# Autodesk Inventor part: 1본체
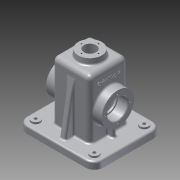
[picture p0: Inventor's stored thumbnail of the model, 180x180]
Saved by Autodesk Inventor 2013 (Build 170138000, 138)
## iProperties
Created: 2016-01
Part Number: 1본체
Material: 알루미늄 6061
Document SubType Name: Modeling
Designer: Administrator
Density: 2.71 g/cm^3
Mass: 927.953 g
Surface Area: 977.096 cm^2
Volume: 342.418 cm^3
Author: Administrator
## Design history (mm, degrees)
sketch "스케치1"
  geometry: L1 (32.5, -32.5)-(-32.5, -32.5); L2 (-32.5, -32.5)-(-32.5, 32.5); L3 (-32.5, 32.5)-(32.5, 32.5); L4 (32.5, 32.5)-(32.5, -32.5); L5 (32.5, -32.5)-(-32.5, 32.5); L6 (-32.5, -32.5)-(32.5, 32.5); 1 further point
  constraints: 12 end point, 2 midpoint, 2 parallel, 1 horizontal, 1 perpendicular
  dimensions: "d0" = 65 distance of L2.end L3.end; "d2" = 65 distance of L1.end L2.end
extrude "돌출1" new body sketch "스케치1" distance "d3" = 110; taper "d4" = 0 deg
feature "쉘1" dims "d5" = 5
sketch "스케치3"
  geometry: L1 (0, 65)-(0, 0) reference; C1 r 27.5 at (-55, 32.5); 2 further points
  constraints: 1 centre point, 1 horizontal alignment, 1 midpoint
  dimensions: "d6" = 55 diameter of C1; "d7" = 55 distance of point (0, 32.5) C1.centre
extrude "돌출2" join sketch "스케치3" distance "d8" = 15; taper "d9" = 0 deg
hole "구멍1" diameter "d12" = 30; stored, may be unused: countersink angle "d16" = 90 deg, drill point angle "d18" = 0 deg; dims "d10" = 10, "d11" = 10, "d13" = 6, "d14" = 35, "d15" = 17, "d17" = 8
sketch "스케치4"
  geometry: C1 r 17.5 at (0, 0) reference; 2 further points
  constraints: 1 horizontal alignment
  dimensions: "d19" = 21 distance of C1.centre point (-21, 0)
hole "구멍2" sketch "스케치4" at (-21, 0) diameter "d20" = 3.242; stored, may be unused: countersink angle "d24" = 90 deg, drill point angle "d26" = 118 deg; dims "d21" = 8, "d22" = 35, "d23" = 17, "d25" = 10
node "작업 평면1"
sketch "스케치5"
  geometry: C1 r 20 at (0, 0); 1 further point
  constraints: 1 centre point, 1 coincident
  dimensions: "d31" = 40 diameter of C1
extrude "돌출3" join sketch "스케치5" stored distance "d32" = 15; taper "d33" = 5 deg
sketch "스케치6"
  geometry: C1 r 20 at (0, 0) reference; C2 r 10.5 at (0, 0)
  constraints: 1 centre point, 1 coincident
  dimensions: "d34" = 21 diameter of C2
extrude "돌출4" cut sketch "스케치6" stored distance "d35" = 15; taper "d36" = 0 deg
sketch "스케치7"
  geometry: C1 r 10.5 at (0, 0) reference; 1 further point
  constraints: 1 horizontal alignment
  dimensions: "d37" = 14.5 distance of point (14.5, 0) C1.centre
hole "구멍3" sketch "스케치7" at (14.5, 0) diameter "d38" = 2.459; stored, may be unused: countersink angle "d42" = 90 deg, drill point angle "d44" = 118 deg; dims "d39" = 7, "d40" = 35, "d41" = 17, "d43" = 9
sketch "스케치8"
  geometry: L1 (-65, 57.5)-(65, 57.5); L2 (65, 57.5)-(65, -57.5); L3 (65, -57.5)-(-65, -57.5); L4 (-65, -57.5)-(-65, 57.5); L5 (-65, 57.5)-(65, -57.5); L6 (65, 57.5)-(-65, -57.5); 1 further point
  constraints: 12 end point, 2 midpoint, 2 parallel, 1 horizontal, 1 perpendicular
  dimensions: "d48" = 130 distance of L1.start L1.end; "d50" = 115 distance of L1.end L2.end
extrude "돌출5" join sketch "스케치8" distance "d51" = 10; taper "d52" = 0 deg
fillet "모깎기1" dims "d53" = 15
sketch "스케치10"
  geometry: C1 r 7.5 at (-50, 42.5); C2 r 7.5 at (50, 42.5); C3 r 7.5 at (50, -42.5); C4 r 7.5 at (-50, -42.5); A1 r 15 centre (50, -42.5) between (50, -57.5) and (65, -42.5) reference; A2 r 15 centre (50, 42.5) between (65, 42.5) and (50, 57.5) reference; A3 r 15 centre (-50, 42.5) between (-50, 57.5) and (-65, 42.5) reference; A4 r 15 centre (-50, -42.5) between (-65, -42.5) and (-50, -57.5) reference; 1 further point
  constraints: 4 centre point, 4 coincident
  dimensions: "d54" = 15 diameter of C1; "d55" = 15 diameter of C2; "d56" = 15 diameter of C3; "d57" = 15 diameter of C4
extrude "돌출6" join sketch "스케치10" distance "d58" = 3; taper "d59" = 0 deg
sketch "스케치11"
  geometry: L1 (-50, -57.5)-(50, -57.5) reference; L2 (65, -42.5)-(65, 42.5) reference; L3 (50, 57.5)-(-50, 57.5) reference; L4 (-65, 42.5)-(-65, -42.5) reference; L5 (50, -52.5)-(-50, -52.5); L6 (-60, -42.5)-(-60, 42.5); L7 (-50, 52.5)-(50, 52.5); L8 (60, 42.5)-(60, -42.5); A1 r 15 centre (-50, -42.5) between (-65, -42.5) and (-50, -57.5) reference; A2 r 15 centre (50, -42.5) between (50, -57.5) and (65, -42.5) reference; A3 r 15 centre (50, 42.5) between (65, 42.5) and (50, 57.5) reference; A4 r 15 centre (-50, 42.5) between (-50, 57.5) and (-65, 42.5) reference; A5 r 10 centre (-50, -42.5) between (-60, -42.5) and (-50, -52.5); A6 r 10 centre (-50, 42.5) between (-50, 52.5) and (-60, 42.5); A7 r 10 centre (50, 42.5) between (60, 42.5) and (50, 52.5); A8 r 10 centre (50, -42.5) between (50, -52.5) and (60, -42.5); 1 further point
  constraints: 8 end point, 8 point on circle, 4 centre point, 7 other
  dimensions: "d60" = 5 distance between parallel lines of L5 L1
extrude "돌출7" join sketch "스케치11" distance "d62" = 2; taper "d63" = 0 deg
sketch "스케치12"
  geometry: A1 r 10 centre (-50, -42.5) between (-60, -42.5) and (-50, -52.5) reference; A2 r 10 centre (50, -42.5) between (50, -52.5) and (60, -42.5) reference; A3 r 10 centre (50, 42.5) between (60, 42.5) and (50, 52.5) reference; A4 r 10 centre (-50, 42.5) between (-50, 52.5) and (-60, 42.5) reference; 1 further point
hole "구멍4" sketch "스케치12" at (50, -42.5), (-50, -42.5), (-50, 42.5), (50, 42.5) diameter "d64" = 5; stored, may be unused: countersink angle "d68" = 90 deg, drill point angle "d70" = 118 deg; dims "d65" = 7, "d66" = 35, "d67" = 17, "d69" = 9
sketch "스케치17"
  geometry: L1 (32.5, 82.5)-(47.5, 82.5) reference; L2 (47.5, 82.5)-(47.5, 77.621) reference; L3 (47.5, 77.621)-(37.5, 77.621) reference; L4 (37.5, 77.621)-(36.526, 76) reference; L5 (36.526, 76)-(37.5, 74.379) reference; L6 (37.5, 74.379)-(47.5, 74.379) reference; L7 (47.5, 74.379)-(47.5, 72.5) reference; L8 (47.5, 72.5)-(30.5, 72.5) reference; L9 (30.5, 72.5)-(30.5, 70) reference; L10 (30.5, 70)-(27.5, 70) reference; L11 (27.5, 70)-(27.5, 105) reference; L12 (27.5, 105)-(10.5, 105) reference; L13 (10.5, 105)-(10.5, 120) reference; L14 (10.5, 120)-(13.271, 120) reference; L15 (13.271, 120)-(13.271, 111) reference; L16 (13.271, 111)-(14.5, 110.261) reference; L17 (14.5, 110.261)-(15.73, 111) reference; L18 (15.73, 111)-(15.73, 120) reference; L19 (15.73, 120)-(20, 120) reference; L20 (20, 120)-(20.875, 110) reference; L21 (20.875, 110)-(32.5, 110) reference; L22 (32.5, 110)-(32.5, 82.5) reference; L23 (-36.526, 34)-(-37.5, 35.621) reference; L24 (-37.5, 35.621)-(-47.5, 35.621) reference; L25 (-47.5, 35.621)-(-47.5, 37.5) reference; L26 (-47.5, 37.5)-(-30.5, 37.5) reference; L27 (-30.5, 37.5)-(-30.5, 40) reference; L28 (-30.5, 40)-(-27.5, 40) reference; L29 (-27.5, 40)-(-27.5, 10) reference; L30 (-27.5, 10)-(27.5, 10) reference; L31 (27.5, 10)-(27.5, 40) reference; L32 (27.5, 40)-(30.5, 40) reference; L33 (30.5, 40)-(30.5, 37.5) reference; L34 (30.5, 37.5)-(47.5, 37.5) reference; L35 (47.5, 37.5)-(47.5, 35.621) reference; L36 (47.5, 35.621)-(37.5, 35.621) reference; L37 (37.5, 35.621)-(36.526, 34) reference; L38 (36.526, 34)-(37.5, 32.379) reference; L39 (37.5, 32.379)-(47.5, 32.379) reference; L40 (47.5, 32.379)-(47.5, 27.5) reference; L41 (47.5, 27.5)-(32.5, 27.5) reference; L42 (32.5, 27.5)-(32.5, 10) reference; L43 (32.5, 10)-(65, 10) reference; L44 (65, 10)-(65, -2) reference; L45 (-65, -2)-(-65, 10) reference; L46 (-65, 10)-(-32.5, 10) reference; L47 (-32.5, 10)-(-32.5, 27.5) reference; L48 (-32.5, 27.5)-(-47.5, 27.5) reference; L49 (-47.5, 27.5)-(-47.5, 32.379) reference; L50 (-47.5, 32.379)-(-37.5, 32.379) reference; L51 (-37.5, 32.379)-(-36.526, 34) reference; L52 (-37.5, 74.379)-(-36.526, 76) reference; L53 (-36.526, 76)-(-37.5, 77.621) reference; L54 (-37.5, 77.621)-(-47.5, 77.621) reference; L55 (-47.5, 77.621)-(-47.5, 82.5) reference; L56 (-47.5, 82.5)-(-32.5, 82.5) reference; L57 (-32.5, 82.5)-(-32.5, 110) reference; L58 (-32.5, 110)-(-20.875, 110) reference; L59 (-20.875, 110)-(-20, 120) reference; L60 (-20, 120)-(-15.73, 120) reference; L61 (-15.73, 120)-(-15.73, 111) reference; L62 (-15.73, 111)-(-14.5, 110.261) reference; L63 (-14.5, 110.261)-(-13.271, 111) reference; L64 (-13.271, 111)-(-13.271, 120) reference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; 1 further point
  constraints: 8 end point, 2 parallel, 1 horizontal, 1 perpendicular
  dimensions: "d106" = 10 distance of L42.end L74.end; "d107" = 4 distance between parallel lines of L41 L76
extrude "돌출10" join sketch "스케치17" stored distance "d108" = 6; taper "d109" = 0 deg
sketch "스케치14"
  geometry: L1 (-20.875, 110)-(-20, 120) reference; L2 (-20, 120)-(-15.73, 120) reference; L3 (-15.73, 120)-(-15.73, 111) reference; L4 (-15.73, 111)-(-14.5, 110.261) reference; L5 (-14.5, 110.261)-(-13.271, 111) reference; L6 (-13.271, 111)-(-13.271, 120) reference; L7 (-13.271, 120)-(-10.5, 120) reference; L8 (-10.5, 120)-(-10.5, 105) reference; L9 (-10.5, 105)-(-27.5, 105) reference; L10 (-27.5, 105)-(-27.5, 10) reference; L11 (-27.5, 10)-(27.5, 10) reference; L12 (27.5, 10)-(27.5, 105) reference; L13 (27.5, 105)-(10.5, 105) reference; L14 (10.5, 105)-(10.5, 120) reference; L15 (10.5, 120)-(13.271, 120) reference; L16 (13.271, 120)-(13.271, 111) reference; L17 (13.271, 111)-(14.5, 110.261) reference; L18 (14.5, 110.261)-(15.73, 111) reference; L19 (15.73, 111)-(15.73, 120) reference; L20 (15.73, 120)-(20, 120) reference; L21 (20, 120)-(20.875, 110) reference; L22 (20.875, 110)-(32.5, 110) reference; L23 (32.5, 110)-(32.5, 10) reference; L24 (32.5, 10)-(57.5, 10) reference; L25 (57.5, 10)-(57.5, -2) reference; L26 (-57.5, -2)-(-57.5, 10) reference; L27 (-57.5, 10)-(-32.5, 10) reference; L28 (-32.5, 10)-(-32.5, 110) reference; L29 (-32.5, 110)-(-20.875, 110) reference; L30 (-57.5, 10)-(-42.5, 10) reference; L31 (-32.5, 95.069)-(-47.5, 10); L32 (57.5, -2)-(52.5, -2) reference; L33 (52.5, -2)-(52.5, 0) reference; L34 (52.5, 0)-(-52.5, 0) reference; L35 (-52.5, 0)-(-52.5, -2) reference; L36 (-52.5, -2)-(-57.5, -2) reference; 1 further point
  constraints: 2 end point, 2 point on line
  dimensions: "d79" = 10 distance of L26.end L31.end; "d80" = 10 deg angle of L26 L31
feature "리브1" sketch "스케치14" dims "d81" = 1, "d82" = 10, "d83" = 0, "d84" = 0, "d85" = 1, "d86" = 1
sketch "스케치15"
  geometry: L1 (100, 0)-(0, 0) reference; L2 (-10, 12.5)-(-10, 52.5) reference; 4 further points
  constraints: 1 other
  dimensions: "d87" = 32.5 distance from line of point (17, 32.5) L1; "d88" = 27 distance from line of L2 point (17, 32.5)
fillet "모깎기2" dims "d89" = 8
fillet "모깎기3" dims "d90" = 8
chamfer "모따기1" distance "d93" = 1; stored, may be unused: second distance "d94" = 2, angle "d95" = 45 deg
fillet "모깎기6" dims "d96" = 0.3
fillet "모깎기7" dims "d97" = 3
fillet "모깎기8" dims "d98" = 3
fillet "모깎기10" dims "d110" = 3
fillet "모깎기11" dims "d111" = 3
sketch "스케치18"
  geometry: L1 (27.5, 27.5)-(-27.5, 27.5); L2 (-27.5, 27.5)-(-27.5, -27.5); L3 (-27.5, -27.5)-(27.5, -27.5); L4 (27.5, -27.5)-(27.5, 27.5); L5 (27.5, 27.5)-(-27.5, -27.5); L6 (-27.5, 27.5)-(27.5, -27.5); 1 further point
  constraints: 12 end point, 2 midpoint, 2 parallel, 1 horizontal, 1 perpendicular
  dimensions: "d114" = 55 distance of L2.end L3.end; "d116" = 55 distance of L1.end L2.end
extrude "돌출11" cut sketch "스케치18" stored distance "d117" = 6; taper "d118" = 0 deg
fillet "모깎기14" dims "d119" = 3
fillet "모깎기15" dims "d120" = 3
feature "엠보싱1" dims "d10" = 10, "d11" = 10, "d121" = 0.5, "d122" = 0
fillet "모깎기9" dims "d99" = 3
node "솔리드1"
pattern_circular "원형 패턴1" dims angle "d28" = 360 deg
mirror "대칭1"
pattern_circular "원형 패턴2" dims angle "d46" = 360 deg
mirror "대칭2"
mirror "대칭3"
node "절단 모서리 투영2"
node "절단 모서리 투영4"
